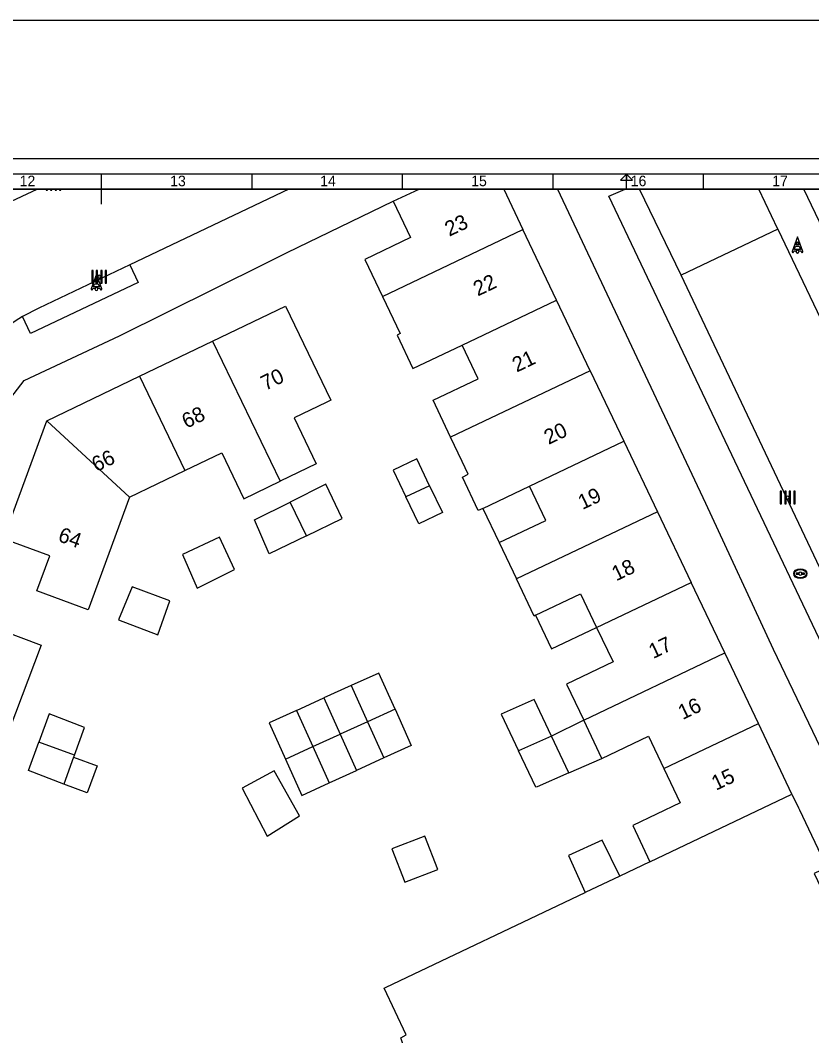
# Model space of a CAD drawing. Extents: x 192664 to 192925, y 446334 to 446521.
# Drawn here: x 192785.3 to 192837.8, y 446453.5 to 446521 of the extents above; entities that cross this region are included whole.
import ezdxf

# ---------------------------------------------------------------- set-up
doc = ezdxf.new("R2010")
doc.units = 0
for name, color, linetype in [('1010 viewport', 7, 'Continuous'), ('bovenleidingmast', 7, 'Continuous'), ('huisnummerreeks BGT', 7, 'Continuous'), ('inspectie-   rioolput', 7, 'Continuous'), ('kant open verharding', 7, 'Continuous'), ('kant verharding', 7, 'Continuous'), ('kolk', 7, 'Continuous'), ('Luifel', 7, 'Continuous'), ('pand op maaiveld vlak', 7, 'Continuous'), ('verkeerseiland - berm', 7, 'Continuous'), ('X-XX-AL-TEKENBLAD-S', 7, 'Continuous'), ('X-XX-AL-TEKENBLAD_KADER-G', 7, 'Continuous')]:
    doc.layers.add(name, color=color, linetype=linetype)

msp = doc.modelspace()

# ---------------------------------------------------------------- linework, layer by layer
at = {"layer": '1010 viewport'}
msp.add_lwpolyline([(192675.743, 446509.756), (192860.643, 446509.756), (192860.643, 446345.556), (192675.743, 446345.556)], close=True, dxfattribs=at)
at = {"layer": 'bovenleidingmast'}
for p, q in [((192836.896, 446506.571), (192836.555, 446505.598)), ((192837.255, 446505.598), (192836.914, 446506.571)), ((192790.32, 446504.087), (192789.979, 446503.114)), ((192790.679, 446503.114), (192790.338, 446504.087))]:
    msp.add_line(p, q, dxfattribs=at)
for points in [[(192836.914, 446506.268), (192836.992, 446506.048), (192836.818, 446506.048), (192836.896, 446506.268)], [(192836.649, 446505.565), (192836.678, 446505.648), (192836.818, 446505.648)], [(192836.992, 446505.648), (192837.132, 446505.648), (192837.161, 446505.565)], [(192790.338, 446503.784), (192790.416, 446503.564), (192790.242, 446503.564), (192790.32, 446503.784)], [(192790.073, 446503.081), (192790.102, 446503.164), (192790.242, 446503.164)], [(192790.416, 446503.164), (192790.556, 446503.164), (192790.585, 446503.081)]]:
    msp.add_lwpolyline(points, dxfattribs=at)
for points in [[(192837.027, 446505.948), (192837.097, 446505.748), (192836.713, 446505.748), (192836.783, 446505.948)], [(192790.451, 446503.464), (192790.521, 446503.264), (192790.137, 446503.264), (192790.207, 446503.464)]]:
    msp.add_lwpolyline(points, close=True, dxfattribs=at)
for centre, radius, start, end in [((192836.905, 446506.568), 0.01, 19.29005, 160.70995), ((192836.905, 446506.265), 0.01, 19.29005, 160.70995), ((192836.602, 446505.581), 0.05, 160.70995, 340.70995), ((192836.905, 446505.598), 0.1, 0, 180), ((192836.905, 446505.598), 0.1, 180, 0), ((192836.905, 446505.598), 0.1, 30, 150), ((192837.208, 446505.581), 0.05, 199.29005, 19.29005), ((192790.329, 446504.084), 0.01, 19.29005, 160.70995), ((192790.329, 446503.781), 0.01, 19.29005, 160.70995), ((192790.026, 446503.097), 0.05, 160.70995, 340.70995), ((192790.329, 446503.114), 0.1, 0, 180), ((192790.329, 446503.114), 0.1, 180, 0), ((192790.329, 446503.114), 0.1, 30, 150), ((192790.632, 446503.097), 0.05, 199.29005, 19.29005)]:
    msp.add_arc(centre, radius, start, end, dxfattribs=at)
at = {"layer": 'inspectie-   rioolput'}
for p, q in [((192837.001, 446484.225), (192836.844, 446484.225)), ((192836.844, 446484.15), (192837.001, 446484.15)), ((192837.344, 446484.225), (192837.187, 446484.225)), ((192837.187, 446484.15), (192837.344, 446484.15))]:
    msp.add_line(p, q, dxfattribs=at)
for centre, radius, start, end in [((192836.844, 446484.187), 0.0375, 90, 270), ((192837.094, 446484.187), 0.1, 0, 180), ((192837.094, 446484.187), 0.1, 157.97569, 180), ((192837.094, 446484.187), 0.1, 180, 202.02431), ((192837.094, 446484.187), 0.1, 180, 0), ((192837.094, 446484.187), 0.1, 0, 22.02431), ((192837.094, 446484.187), 0.1, 337.97569, 0), ((192837.344, 446484.187), 0.0375, 270, 90)]:
    msp.add_arc(centre, radius, start, end, dxfattribs=at)
for major_axis, ratio in [((-0.442, 0), 0.73911), ((-0.392, 0), 0.689655)]:
    msp.add_ellipse((192837.094, 446484.187), major_axis=major_axis, ratio=ratio, dxfattribs=at)
at = {"layer": 'kant open verharding'}
for p, q in [((192803.101, 446509.756), (192792.545, 446504.728)), ((192849.384, 446484.404), (192837.327, 446509.756)), ((192835.606, 446507.086), (192829.185, 446504.028)), ((192835.606, 446507.086), (192852.92, 446470.626))]:
    msp.add_line(p, q, dxfattribs=at)
for points in [[(192820.967, 446509.756), (192830.801, 446488.882), (192835.291, 446479.169), (192839.711, 446469.931), (192846.946, 446454.816)], [(192779.53, 446482.124), (192780.051, 446483.746), (192784.415, 446495.597), (192785.528, 446497.018), (192791.864, 446500), (192801.451, 446504.762), (192802.996, 446505.531), (192810.052, 446508.944)]]:
    msp.add_lwpolyline(points, dxfattribs=at)
msp.add_arc((192789.771, 446494.09), 8.418, 121.18376, 153.13609, dxfattribs=at)
at = {"layer": 'kant verharding'}
for p, q in [((192784.351, 446508.796), (192786.378, 446509.756)), ((192829.185, 446504.028), (192826.401, 446509.756)), ((192835.606, 446507.086), (192834.338, 446509.756)), ((192847.908, 446464.417), (192829.185, 446504.028))]:
    msp.add_line(p, q, dxfattribs=at)
msp.add_lwpolyline([(192847.34, 446464.645), (192845.844, 446464.076), (192824.376, 446509.29), (192825.458, 446509.756)], dxfattribs=at)
at = {"layer": 'kolk'}
for points in [[(192787.071, 446509.756), (192786.986, 446509.756), (192786.986, 446509.684), (192787.071, 446509.684)], [(192787.369, 446509.756), (192787.284, 446509.756), (192787.284, 446509.684), (192787.369, 446509.684)], [(192787.666, 446509.756), (192787.581, 446509.756), (192787.581, 446509.684), (192787.666, 446509.684)], [(192787.964, 446509.756), (192787.879, 446509.756), (192787.879, 446509.684), (192787.964, 446509.684)], [(192790.101, 446503.927), (192790.101, 446504.352), (192790.016, 446504.352), (192790.016, 446503.927), (192790.016, 446503.502), (192790.101, 446503.502)], [(192790.399, 446503.927), (192790.399, 446504.352), (192790.314, 446504.352), (192790.314, 446503.927), (192790.314, 446503.502), (192790.399, 446503.502)], [(192790.696, 446503.927), (192790.696, 446504.352), (192790.611, 446504.352), (192790.611, 446503.927), (192790.611, 446503.502), (192790.696, 446503.502)], [(192790.994, 446503.927), (192790.994, 446504.352), (192790.909, 446504.352), (192790.909, 446503.927), (192790.909, 446503.502), (192790.994, 446503.502)], [(192835.85, 446489.244), (192835.85, 446489.669), (192835.765, 446489.669), (192835.765, 446489.244), (192835.765, 446488.819), (192835.85, 446488.819)], [(192836.148, 446489.244), (192836.148, 446489.669), (192836.063, 446489.669), (192836.063, 446489.244), (192836.063, 446488.819), (192836.148, 446488.819)], [(192836.445, 446489.244), (192836.445, 446489.669), (192836.36, 446489.669), (192836.36, 446489.244), (192836.36, 446488.819), (192836.445, 446488.819)], [(192836.743, 446489.244), (192836.743, 446489.669), (192836.658, 446489.669), (192836.658, 446489.244), (192836.658, 446488.819), (192836.743, 446488.819)]]:
    msp.add_lwpolyline(points, close=True, dxfattribs=at)
for centre, start, end in [((192790.505, 446503.927), 0, 180), ((192790.505, 446503.927), 180, 0), ((192836.254, 446489.244), 0, 180), ((192836.254, 446489.244), 180, 0)]:
    msp.add_arc(centre, 0.1, start, end, dxfattribs=at)
at = {"layer": 'Luifel'}
for p, q in [((192815.996, 446488.526), (192817.077, 446486.256)), ((192822.699, 446474.451), (192820.567, 446473.387)), ((192821.719, 446470.955), (192823.909, 446471.909))]:
    msp.add_line(p, q, dxfattribs=at)
for points in [[(192812.464, 446490.035), (192813.315, 446488.246), (192811.741, 446487.497), (192810.89, 446489.286)], [(192819.507, 446481.42), (192820.568, 446479.192), (192823.558, 446480.616)], [(192788.813, 446471.993), (192790.383, 446471.415), (192789.719, 446469.611), (192788.149, 446470.189)]]:
    msp.add_lwpolyline(points, dxfattribs=at)
at = {"layer": 'pand op maaiveld vlak'}
for p, q in [((192810.052, 446508.944), (192811.759, 446509.756)), ((192817.385, 446509.756), (192818.666, 446507.065)), ((192809.329, 446502.618), (192818.666, 446507.065)), ((192820.9, 446502.373), (192818.666, 446507.065)), ((192814.631, 446499.387), (192820.9, 446502.373)), ((192823.135, 446497.681), (192820.9, 446502.373)), ((192793.189, 446497.308), (192798.04, 446499.643)), ((192798.04, 446499.643), (192802.523, 446490.331)), ((192823.135, 446497.681), (192813.859, 446493.264)), ((192823.135, 446497.681), (192825.369, 446492.989)), ((192787.037, 446494.347), (192793.189, 446497.308)), ((192793.189, 446497.308), (192796.205, 446491.041)), ((192792.525, 446489.271), (192787.037, 446494.347)), ((192819.094, 446490.001), (192825.369, 446492.989)), ((192825.369, 446492.989), (192827.603, 446488.298)), ((192825.369, 446492.989), (192827.603, 446488.298)), ((192792.525, 446489.271), (192796.205, 446491.041)), ((192812.464, 446490.035), (192810.89, 446489.286)), ((192815.996, 446488.526), (192819.094, 446490.001)), ((192804.284, 446486.712), (192803.202, 446488.946)), ((192827.603, 446488.298), (192818.23, 446483.834)), ((192827.603, 446488.298), (192829.837, 446483.606)), ((192817.077, 446486.256), (192818.23, 446483.834)), ((192823.558, 446480.616), (192829.837, 446483.606)), ((192832.071, 446478.914), (192829.837, 446483.606)), ((192822.699, 446474.451), (192832.071, 446478.914)), ((192834.306, 446474.222), (192832.071, 446478.914)), ((192807.259, 446476.75), (192805.437, 446475.926)), ((192807.259, 446476.75), (192808.343, 446474.342)), ((192803.614, 446475.101), (192805.437, 446475.926)), ((192805.437, 446475.926), (192806.523, 446473.515)), ((192803.614, 446475.101), (192804.701, 446472.687)), ((192810.165, 446475.169), (192808.343, 446474.342)), ((192823.909, 446471.909), (192822.699, 446474.451)), ((192808.343, 446474.342), (192806.523, 446473.515)), ((192808.343, 446474.342), (192809.428, 446471.933)), ((192828.023, 446471.23), (192834.306, 446474.222)), ((192836.54, 446469.53), (192834.306, 446474.222)), ((192804.701, 446472.687), (192806.523, 446473.515)), ((192806.523, 446473.515), (192807.608, 446471.104)), ((192820.567, 446473.387), (192818.372, 446472.42)), ((192821.719, 446470.955), (192820.567, 446473.387)), ((192788.861, 446472.123), (192786.504, 446472.992)), ((192802.88, 446471.86), (192804.701, 446472.687)), ((192804.701, 446472.687), (192805.787, 446470.274)), ((192788.813, 446471.993), (192788.149, 446470.189)), ((192788.861, 446472.123), (192788.813, 446471.993)), ((192809.428, 446471.933), (192807.608, 446471.104)), ((192805.787, 446470.274), (192807.608, 446471.104)), ((192827.098, 446465.038), (192836.54, 446469.53)), ((192827.098, 446465.038), (192825.097, 446464.085)), ((192825.097, 446464.085), (192822.797, 446462.99))]:
    msp.add_line(p, q, dxfattribs=at)
for points in [[(192810.052, 446508.944), (192811.2, 446506.531), (192808.156, 446505.081), (192809.329, 446502.618)], [(192809.329, 446502.618), (192810.506, 446500.147), (192810.302, 446500.05), (192811.352, 446497.825), (192814.631, 446499.387)], [(192798.04, 446499.643), (192802.893, 446501.979), (192805.903, 446495.725), (192805.591, 446495.575), (192803.461, 446494.549), (192804.933, 446491.491), (192802.523, 446490.331)], [(192813.859, 446493.264), (192812.693, 446495.713), (192815.699, 446497.145), (192814.631, 446499.387)], [(192792.525, 446489.271), (192789.784, 446481.79), (192786.371, 446483.041), (192787.224, 446485.369), (192784.159, 446486.492), (192787.037, 446494.347)], [(192815.996, 446488.526), (192815.693, 446488.382), (192814.643, 446490.607), (192815.035, 446490.794), (192814.629, 446491.646), (192813.859, 446493.264)], [(192796.205, 446491.041), (192798.647, 446492.217), (192800.113, 446489.171), (192802.523, 446490.331)], [(192812.464, 446490.035), (192811.612, 446491.824), (192810.038, 446491.074), (192810.89, 446489.286)], [(192804.284, 446486.712), (192806.652, 446487.86), (192805.57, 446490.129), (192803.202, 446488.946)], [(192817.077, 446486.256), (192820.174, 446487.726), (192819.094, 446490.001)], [(192804.284, 446486.712), (192801.813, 446485.514), (192800.833, 446487.762), (192803.202, 446488.946)], [(192799.494, 446484.467), (192798.505, 446486.618), (192796.055, 446485.455), (192797.016, 446483.224), (192799.494, 446484.467)], [(192795.209, 446482.388), (192792.694, 446483.304), (192791.799, 446481.108), (192794.407, 446480.126), (192795.209, 446482.388)], [(192819.507, 446481.42), (192819.403, 446481.371), (192818.23, 446483.834)], [(192819.507, 446481.42), (192822.497, 446482.844), (192823.558, 446480.616)], [(192779.53, 446482.124), (192786.658, 446479.438), (192784.508, 446473.734)], [(192823.558, 446480.616), (192824.653, 446478.317), (192821.559, 446476.844), (192822.699, 446474.451)], [(192810.165, 446475.169), (192809.081, 446477.575), (192807.259, 446476.75)], [(192820.567, 446473.387), (192819.416, 446475.818), (192817.218, 446474.857), (192818.372, 446472.42)], [(192803.614, 446475.101), (192801.792, 446474.276), (192802.88, 446471.86)], [(192810.165, 446475.169), (192811.248, 446472.763), (192809.428, 446471.933)], [(192788.861, 446472.123), (192789.539, 446473.962), (192787.186, 446474.872), (192786.504, 446472.992)], [(192823.909, 446471.909), (192826.999, 446473.381), (192828.023, 446471.23)], [(192788.149, 446470.189), (192785.822, 446471.111), (192786.504, 446472.992)], [(192821.719, 446470.955), (192819.611, 446470.02), (192819.526, 446469.983), (192818.372, 446472.42)], [(192802.88, 446471.86), (192803.967, 446469.444), (192805.787, 446470.274)], [(192803.82, 446468.077), (192802.143, 446471.084), (192800.001, 446469.917), (192801.666, 446466.73), (192803.82, 446468.077)], [(192828.023, 446471.23), (192829.112, 446468.943), (192825.955, 446467.439), (192827.098, 446465.038)], [(192836.54, 446469.53), (192836.973, 446468.62), (192837.036, 446468.487), (192838.86, 446464.658), (192838.011, 446464.254), (192843.76, 446452.181), (192841.215, 446450.969), (192841.788, 446449.766), (192840.974, 446449.379), (192840.403, 446450.578), (192839.983, 446450.377), (192841.046, 446448.145), (192838.693, 446441.612)], [(192810.813, 446463.676), (192813.005, 446464.519), (192812.149, 446466.745), (192809.957, 446465.901), (192810.813, 446463.676)], [(192825.097, 446464.085), (192823.934, 446466.46), (192821.691, 446465.451), (192822.797, 446462.99)], [(192811.054, 446451.801), (192810.545, 446453.32), (192810.916, 446453.523), (192809.437, 446456.628), (192809.575, 446456.694), (192822.797, 446462.99)]]:
    msp.add_lwpolyline(points, dxfattribs=at)
at = {"layer": 'verkeerseiland - berm'}
for points in [[(192792.545, 446504.728), (192793.101, 446503.55), (192785.941, 446500.151), (192785.412, 446501.292)], [(192792.545, 446504.728), (192786.498, 446501.848), (192785.412, 446501.292)]]:
    msp.add_lwpolyline(points, dxfattribs=at)
at = {"layer": 'X-XX-AL-TEKENBLAD-S'}
for p, q in [((192909.543, 446511.756), (192671.743, 446511.756)), ((192908.543, 446510.756), (192674.743, 446510.756)), ((192800.643, 446510.756), (192800.643, 446509.756)), ((192810.643, 446510.756), (192810.643, 446509.756)), ((192820.643, 446510.756), (192820.643, 446509.756)), ((192825.543, 446509.756), (192825.543, 446510.756)), ((192830.643, 446510.756), (192830.643, 446509.756))]:
    msp.add_line(p, q, dxfattribs=at)
for points in [[(192790.643, 446510.756), (192790.643, 446508.756)], [(192825.543, 446510.356), (192825.543, 446510.756), (192825.143, 446510.356), (192825.543, 446510.356)], [(192825.543, 446510.756), (192825.543, 446510.356), (192825.943, 446510.356), (192825.543, 446510.756)]]:
    msp.add_lwpolyline(points, dxfattribs=at)
msp.add_lwpolyline([(192675.743, 446345.556), (192907.543, 446345.556), (192907.543, 446509.756), (192675.743, 446509.756)], close=True, dxfattribs=at)
at = {"layer": 'X-XX-AL-TEKENBLAD_KADER-G'}
msp.add_lwpolyline([(192664.22, 446520.974), (192925.029, 446520.974), (192925.029, 446333.894), (192664.22, 446333.894)], close=True, dxfattribs=at)

# ---------------------------------------------------------------- texts
at = {"layer": 'huisnummerreeks BGT'}
for s, rotation, p in [('23', 25.5, (192813.772, 446506.583)), ('22', 25.5, (192815.664, 446502.609)), ('21', 25.5, (192818.252, 446497.553)), ('70', 25.7, (192801.548, 446496.337)), ('68', 25.7, (192796.306, 446493.815)), ('20', 25.5, (192820.365, 446492.744)), ('66', 25.7, (192790.317, 446490.931)), ('19', 25.5, (192822.623, 446488.417)), ('64', 339.9, (192787.709, 446486.374)), ('18', 25.5, (192824.862, 446483.673)), ('17', 25.5, (192827.318, 446478.508)), ('16', 25.5, (192829.272, 446474.452)), ('15', 25.5, (192831.492, 446469.75))]:
    msp.add_text(s, height=1, rotation=rotation, dxfattribs=at).set_placement(p)
at = {"layer": 'X-XX-AL-TEKENBLAD-S'}
for s, p in [('12', (192785.224, 446509.945)), ('13', (192795.223, 446509.945)), ('14', (192805.189, 446509.945)), ('15', (192815.224, 446509.945)), ('16', (192825.824, 446509.945)), ('17', (192835.224, 446509.945))]:
    msp.add_text(s, height=0.7, dxfattribs=at).set_placement(p)

doc.saveas('drawing.dxf')
